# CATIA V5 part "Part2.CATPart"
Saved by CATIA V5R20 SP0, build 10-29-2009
Part number: Part2
Bounding box of the stored display mesh (mm): x -170 to 170, y -130 to 130, z 0 to 6
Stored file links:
  C:\Users\12584\Desktop\新建文件夹 (3)\Part2.CATPart
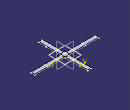
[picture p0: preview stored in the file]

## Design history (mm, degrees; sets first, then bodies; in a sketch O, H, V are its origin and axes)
Body1 (main body)
  Sketch1 on xy-plane, origin (0, 0, 0), H (1, 0, 0), V (0, 1, 0)
    line L1 (-100, 10) -> (-10, 10)
    line L2 (100, -10) -> (10, -10)
    line L3 (10, 90) -> (10, 10)
    line L4 (-10, -90) -> (-10, -10)
    line L5 (10, -10) -> (10, -90)
    point P10 (10, 10)
    point P11 (-10, 10)
    line L6 (10, 10) -> (100, 10)
    line L7 (-10, 10) -> (-10, 90)
    point P12 (-10, -10)
    line L8 (-10, -10) -> (-100, -10)
    line L9 (100, 10) -> (170, 10)
    line L10 (170, 10) -> (170, -10)
    line L11 (170, -10) -> (100, -10)
    line L12 (-100, -10) -> (-170, -10)
    line L13 (-170, -10) -> (-170, 10)
    line L14 (-170, 10) -> (-100, 10)
    line L15 (10, 90) -> (10, 130)
    line L16 (10, 130) -> (-10, 130)
    line L17 (-10, 130) -> (-10, 90)
    line L18 (10, -90) -> (10, -130)
    line L19 (10, -130) -> (-10, -130)
    line L20 (-10, -130) -> (-10, -90)
    horizontal: L1 H, L2 H, L6 H, L8 H, L9 H, L11 H, L12 H, L14 H, L16 H, L19 H
    vertical: L3 V, L4 V, L5 V, L7 V, L10 V, L13 V, L15 V, L17 V, L18 V, L20 V
    coincidence: L1 P10, L3 L5, L4 P11, L1 L6, L2 P12, L4 L7, L2 L8
  Pad1: profile Sketch1, direction (0, 0, 1), length 3
  Plane1: type Offset, RefPlane xy-plane, Offset 3
  Sketch2 on Plane1, origin (0, 0, 3), H (1, 0, 0), V (0, 1, 0)
    circle A1 centre (0, 0) radius 14.1421
  Pad2: profile Sketch2, direction (0, 0, 1), length 3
